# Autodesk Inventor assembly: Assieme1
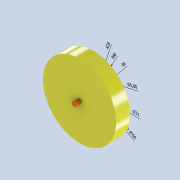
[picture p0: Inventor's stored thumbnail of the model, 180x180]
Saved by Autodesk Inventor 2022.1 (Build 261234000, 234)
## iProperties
Created: 2022-04
Part Number: Assieme1
Document SubType Name: Assembly
Designer: i911900
Author: i911900
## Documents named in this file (6)
- C:\Users\i911900\Desktop\cyclo_medium\56mm v2\Assieme1.iam
- C:\Users\i911900\Desktop\cyclo_medium\56mm v2\disco1.ipt
- C:\Users\i911900\Desktop\cyclo_medium\56mm v2\ruota.ipt
- C:\Users\i911900\Desktop\cyclo_medium\56mm v2\piolo.ipt
- C:\Users\i911900\Desktop\cyclo_medium\56mm v2\albero.ipt
- C:\Users\i911900\Desktop\cyclo_medium\56mm v2\disco2.ipt
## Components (15 placed, 5 different names)
1. disco1:1 — Rigido:4, Rigido:3, Rigido:5, Rigido:6, Rigido:7, Rigido:8, Rigido:9, Rigido:10, Rigido:11, Rigido:12, Rigido:13, Coincidente:1
2. piolo:1 — Rigido:4, Transitorio:2
3. piolo:2 — Rigido:3, Transitorio:1
4. piolo:3 — Rigido:5
5. piolo:4 — Rigido:9
6. piolo:5 — Rigido:10
7. piolo:6 — Rigido:12
8. piolo:7 — Rigido:11
9. piolo:8 — Rigido:7
10. piolo:9 — Rigido:6
11. piolo:10 — Rigido:8
12. piolo:11 — Rigido:13
13. disco2:1 — Coincidente:4
14. ruota:1 — Coincidente:3, Transitorio:1, Transitorio:2
15. albero:1 — Coincidente:1, Coincidente:3, Coincidente:4
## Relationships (16: WeldJoint 11, Mate 3, Transitional 2)
- Rigido:4 [WeldJoint]: disco1:1 ↔ piolo:1
- Rigido:3 [WeldJoint]: disco1:1 ↔ piolo:2
- Rigido:5 [WeldJoint]: disco1:1 ↔ piolo:3
- Rigido:6 [WeldJoint]: disco1:1 ↔ piolo:9
- Rigido:7 [WeldJoint]: disco1:1 ↔ piolo:8
- Rigido:8 [WeldJoint]: disco1:1 ↔ piolo:10
- Rigido:9 [WeldJoint]: disco1:1 ↔ piolo:4
- Rigido:10 [WeldJoint]: disco1:1 ↔ piolo:5
- Rigido:11 [WeldJoint]: disco1:1 ↔ piolo:7
- Rigido:12 [WeldJoint]: disco1:1 ↔ piolo:6
- Rigido:13 [WeldJoint]: disco1:1 ↔ piolo:11
- Coincidente:1 [Mate]: disco1:1 ↔ albero:1
- Coincidente:3 [Mate]: ruota:1 ↔ albero:1
- Coincidente:4 [Mate]: disco2:1 ↔ albero:1
- Transitorio:1: piolo:2 ↔ ruota:1
- Transitorio:2: piolo:1 ↔ ruota:1
